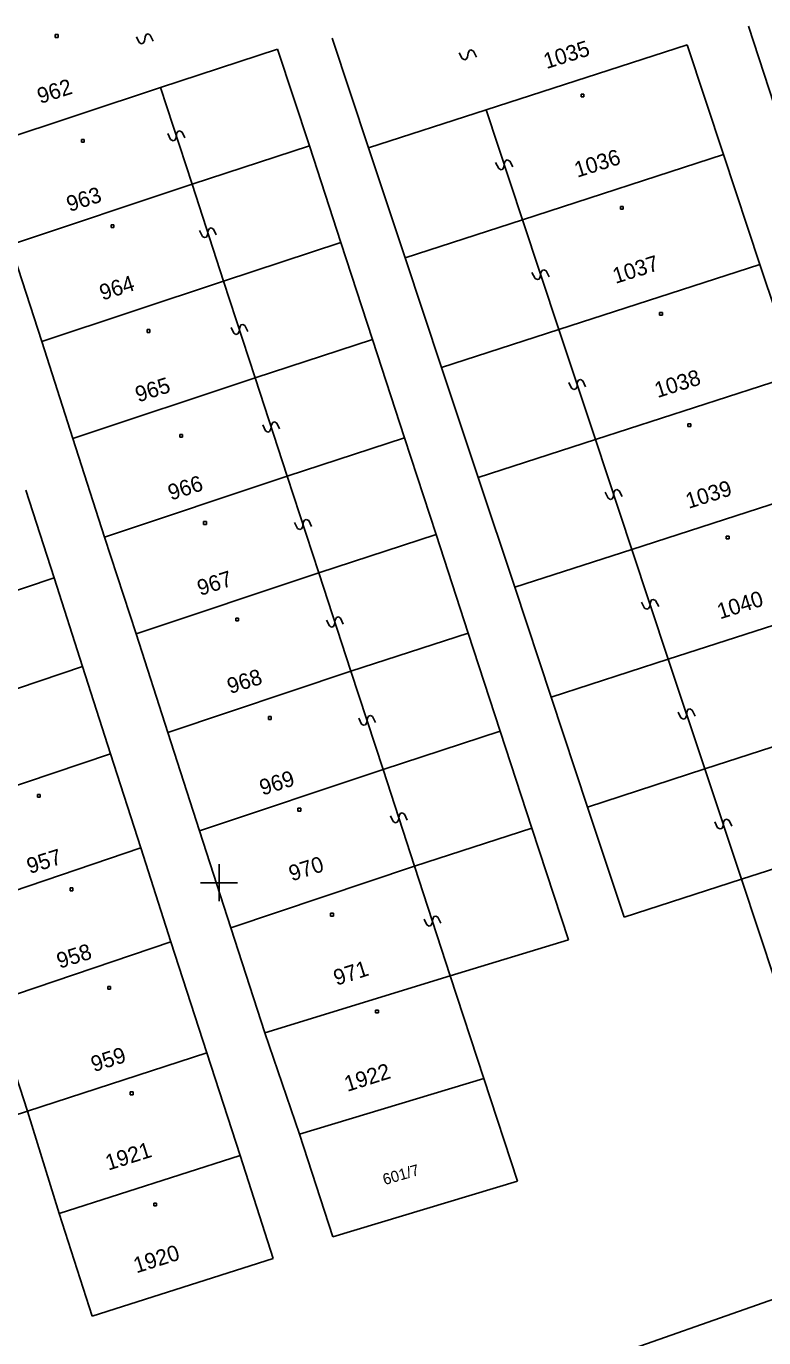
# Model space of a CAD drawing. Extents: x -493352 to -492964, y -1127001 to -1126712.
# Drawn here: x -493236.25 to -493212.33, y -1126754.75 to -1126712.25 of the extents above; entities that cross this region are included whole.
import ezdxf

# ---------------------------------------------------------------- set-up
doc = ezdxf.new("R2010")
doc.units = 0
doc.layers.add('katastrální mapa', color=7, linetype='Continuous')
doc.layers.add('síť', color=7, linetype='Continuous')

msp = doc.modelspace()

# ---------------------------------------------------------------- linework, layer by layer
at = {"layer": 'katastrální mapa'}
for p, q in [((-493212.83, -1126712.25), (-493211.66, -1126715.82)), ((-493235.31, -1126712.52), (-493235.22, -1126712.52)), ((-493235.31, -1126712.61), (-493235.31, -1126712.52)), ((-493235.22, -1126712.61), (-493235.31, -1126712.61)), ((-493235.22, -1126712.52), (-493235.22, -1126712.61)), ((-493232.59, -1126712.78), (-493232.68, -1126712.59)), ((-493232.52, -1126712.82), (-493232.59, -1126712.78)), ((-493232.46, -1126712.8), (-493232.52, -1126712.82)), ((-493232.42, -1126712.73), (-493232.46, -1126712.8)), ((-493232.4, -1126712.59), (-493232.42, -1126712.73)), ((-493232.36, -1126712.52), (-493232.4, -1126712.59)), ((-493232.3, -1126712.5), (-493232.36, -1126712.52)), ((-493232.23, -1126712.54), (-493232.3, -1126712.5)), ((-493232.14, -1126712.73), (-493232.23, -1126712.54)), ((-493226.33, -1126712.64), (-493225.15, -1126716.19)), ((-493221.34, -1126714.96), (-493214.82, -1126712.85)), ((-493214.82, -1126712.85), (-493213.64, -1126716.41)), ((-493231.9, -1126714.23), (-493228.1, -1126712.99)), ((-493228.1, -1126712.99), (-493227.07, -1126716.13)), ((-493222.11, -1126713.3), (-493222.21, -1126713.11)), ((-493221.94, -1126713.25), (-493221.98, -1126713.32)), ((-493221.92, -1126713.11), (-493221.94, -1126713.25)), ((-493221.88, -1126713.04), (-493221.92, -1126713.11)), ((-493221.83, -1126713.02), (-493221.88, -1126713.04)), ((-493221.75, -1126713.06), (-493221.83, -1126713.02)), ((-493221.65, -1126713.25), (-493221.75, -1126713.06)), ((-493222.03, -1126713.34), (-493222.11, -1126713.3)), ((-493221.98, -1126713.32), (-493222.03, -1126713.34)), ((-493237.78, -1126716.19), (-493231.9, -1126714.23)), ((-493231.9, -1126714.23), (-493230.87, -1126717.37)), ((-493218.26, -1126714.45), (-493218.17, -1126714.45)), ((-493218.26, -1126714.54), (-493218.26, -1126714.45)), ((-493218.17, -1126714.54), (-493218.26, -1126714.54)), ((-493218.17, -1126714.45), (-493218.17, -1126714.54)), ((-493225.15, -1126716.19), (-493221.34, -1126714.96)), ((-493221.34, -1126714.96), (-493220.16, -1126718.52)), ((-493231.57, -1126715.92), (-493231.66, -1126715.73)), ((-493231.38, -1126715.73), (-493231.39, -1126715.87)), ((-493231.34, -1126715.66), (-493231.38, -1126715.73)), ((-493231.28, -1126715.64), (-493231.34, -1126715.66)), ((-493231.2, -1126715.68), (-493231.28, -1126715.64)), ((-493231.11, -1126715.87), (-493231.2, -1126715.68)), ((-493234.46, -1126715.92), (-493234.37, -1126715.92)), ((-493234.46, -1126716.01), (-493234.46, -1126715.92)), ((-493234.37, -1126716.01), (-493234.46, -1126716.01)), ((-493234.37, -1126715.92), (-493234.37, -1126716.01)), ((-493231.49, -1126715.96), (-493231.57, -1126715.92)), ((-493231.43, -1126715.94), (-493231.49, -1126715.96)), ((-493231.39, -1126715.87), (-493231.43, -1126715.94)), ((-493230.87, -1126717.37), (-493227.07, -1126716.13)), ((-493227.07, -1126716.13), (-493226.05, -1126719.26)), ((-493225.15, -1126716.19), (-493223.96, -1126719.75)), ((-493220.93, -1126716.86), (-493221.03, -1126716.67)), ((-493220.74, -1126716.67), (-493220.76, -1126716.81)), ((-493220.7, -1126716.6), (-493220.74, -1126716.67)), ((-493220.65, -1126716.58), (-493220.7, -1126716.6)), ((-493220.57, -1126716.62), (-493220.65, -1126716.58)), ((-493220.47, -1126716.81), (-493220.57, -1126716.62)), ((-493220.16, -1126718.52), (-493213.64, -1126716.41)), ((-493213.64, -1126716.41), (-493212.46, -1126719.97)), ((-493220.85, -1126716.9), (-493220.93, -1126716.86)), ((-493220.8, -1126716.88), (-493220.85, -1126716.9)), ((-493220.76, -1126716.81), (-493220.8, -1126716.88)), ((-493236.76, -1126719.33), (-493230.87, -1126717.37)), ((-493230.87, -1126717.37), (-493229.85, -1126720.51)), ((-493216.98, -1126718.09), (-493216.89, -1126718.09)), ((-493216.98, -1126718.18), (-493216.98, -1126718.09)), ((-493216.89, -1126718.18), (-493216.98, -1126718.18)), ((-493216.89, -1126718.09), (-493216.89, -1126718.18)), ((-493233.5, -1126718.68), (-493233.41, -1126718.68)), ((-493233.5, -1126718.77), (-493233.5, -1126718.68)), ((-493233.41, -1126718.77), (-493233.5, -1126718.77)), ((-493233.41, -1126718.68), (-493233.41, -1126718.77)), ((-493230.31, -1126718.8), (-493230.35, -1126718.87)), ((-493230.25, -1126718.78), (-493230.31, -1126718.8)), ((-493230.18, -1126718.82), (-493230.25, -1126718.78)), ((-493223.96, -1126719.75), (-493220.16, -1126718.52)), ((-493220.16, -1126718.52), (-493218.98, -1126722.08)), ((-493230.54, -1126719.06), (-493230.63, -1126718.87)), ((-493230.47, -1126719.1), (-493230.54, -1126719.06)), ((-493230.41, -1126719.08), (-493230.47, -1126719.1)), ((-493230.37, -1126719.01), (-493230.41, -1126719.08)), ((-493230.35, -1126718.87), (-493230.37, -1126719.01)), ((-493230.09, -1126719.01), (-493230.18, -1126718.82)), ((-493236.76, -1126719.33), (-493235.75, -1126722.47)), ((-493229.85, -1126720.51), (-493226.05, -1126719.26)), ((-493226.05, -1126719.26), (-493225.02, -1126722.4)), ((-493223.96, -1126719.75), (-493222.78, -1126723.31)), ((-493218.98, -1126722.08), (-493212.46, -1126719.97)), ((-493212.46, -1126719.97), (-493211.27, -1126723.53)), ((-493219.75, -1126720.42), (-493219.85, -1126720.23)), ((-493219.67, -1126720.46), (-493219.75, -1126720.42)), ((-493219.62, -1126720.44), (-493219.67, -1126720.46)), ((-493219.58, -1126720.37), (-493219.62, -1126720.44)), ((-493219.56, -1126720.23), (-493219.58, -1126720.37)), ((-493219.52, -1126720.16), (-493219.56, -1126720.23)), ((-493219.47, -1126720.14), (-493219.52, -1126720.16)), ((-493219.39, -1126720.18), (-493219.47, -1126720.14)), ((-493219.29, -1126720.37), (-493219.39, -1126720.18)), ((-493235.75, -1126722.47), (-493229.85, -1126720.51)), ((-493229.85, -1126720.51), (-493228.83, -1126723.64)), ((-493215.71, -1126721.52), (-493215.62, -1126721.52)), ((-493215.71, -1126721.61), (-493215.71, -1126721.52)), ((-493215.62, -1126721.61), (-493215.71, -1126721.61)), ((-493215.62, -1126721.52), (-493215.62, -1126721.61)), ((-493232.33, -1126722.08), (-493232.24, -1126722.08)), ((-493232.33, -1126722.17), (-493232.33, -1126722.08)), ((-493232.24, -1126722.17), (-493232.33, -1126722.17)), ((-493232.24, -1126722.08), (-493232.24, -1126722.17)), ((-493229.52, -1126722.2), (-493229.61, -1126722.01)), ((-493229.45, -1126722.24), (-493229.52, -1126722.2)), ((-493229.35, -1126722.14), (-493229.39, -1126722.22)), ((-493229.33, -1126722.01), (-493229.35, -1126722.14)), ((-493229.29, -1126721.93), (-493229.33, -1126722.01)), ((-493229.23, -1126721.91), (-493229.29, -1126721.93)), ((-493229.16, -1126721.95), (-493229.23, -1126721.91)), ((-493229.07, -1126722.14), (-493229.16, -1126721.95)), ((-493222.78, -1126723.31), (-493218.98, -1126722.08)), ((-493218.98, -1126722.08), (-493217.79, -1126725.64)), ((-493235.75, -1126722.47), (-493234.74, -1126725.61)), ((-493229.39, -1126722.22), (-493229.45, -1126722.24)), ((-493228.83, -1126723.64), (-493225.02, -1126722.4)), ((-493225.02, -1126722.4), (-493223.98, -1126725.59)), ((-493222.78, -1126723.31), (-493221.6, -1126726.87)), ((-493234.74, -1126725.61), (-493228.83, -1126723.64)), ((-493228.83, -1126723.64), (-493227.79, -1126726.83)), ((-493218.57, -1126723.98), (-493218.66, -1126723.79)), ((-493218.38, -1126723.79), (-493218.39, -1126723.93)), ((-493218.34, -1126723.72), (-493218.38, -1126723.79)), ((-493218.28, -1126723.7), (-493218.34, -1126723.72)), ((-493218.2, -1126723.74), (-493218.28, -1126723.7)), ((-493218.11, -1126723.93), (-493218.2, -1126723.74)), ((-493217.79, -1126725.64), (-493211.27, -1126723.53)), ((-493218.49, -1126724.02), (-493218.57, -1126723.98)), ((-493218.43, -1126724), (-493218.49, -1126724.02)), ((-493218.39, -1126723.93), (-493218.43, -1126724)), ((-493228.49, -1126725.36), (-493228.58, -1126725.17)), ((-493228.3, -1126725.17), (-493228.32, -1126725.3)), ((-493228.26, -1126725.09), (-493228.3, -1126725.17)), ((-493228.2, -1126725.07), (-493228.26, -1126725.09)), ((-493228.13, -1126725.11), (-493228.2, -1126725.07)), ((-493228.04, -1126725.3), (-493228.13, -1126725.11)), ((-493214.79, -1126725.13), (-493214.7, -1126725.13)), ((-493214.79, -1126725.22), (-493214.79, -1126725.13)), ((-493214.7, -1126725.13), (-493214.7, -1126725.22)), ((-493231.27, -1126725.48), (-493231.18, -1126725.48)), ((-493231.27, -1126725.57), (-493231.27, -1126725.48)), ((-493231.18, -1126725.57), (-493231.27, -1126725.57)), ((-493231.18, -1126725.48), (-493231.18, -1126725.57)), ((-493228.42, -1126725.4), (-493228.49, -1126725.36)), ((-493228.36, -1126725.38), (-493228.42, -1126725.4)), ((-493228.32, -1126725.3), (-493228.36, -1126725.38)), ((-493227.79, -1126726.83), (-493223.98, -1126725.59)), ((-493223.98, -1126725.59), (-493222.96, -1126728.72)), ((-493214.7, -1126725.22), (-493214.79, -1126725.22)), ((-493234.74, -1126725.61), (-493233.71, -1126728.8)), ((-493221.6, -1126726.87), (-493217.79, -1126725.64)), ((-493217.79, -1126725.64), (-493216.61, -1126729.2)), ((-493233.71, -1126728.8), (-493227.79, -1126726.83)), ((-493227.79, -1126726.83), (-493226.76, -1126729.96)), ((-493221.6, -1126726.87), (-493220.41, -1126730.43)), ((-493236.27, -1126727.28), (-493235.35, -1126730.12)), ((-493217.15, -1126727.28), (-493217.19, -1126727.35)), ((-493217.1, -1126727.26), (-493217.15, -1126727.28)), ((-493217.02, -1126727.3), (-493217.1, -1126727.26)), ((-493216.92, -1126727.49), (-493217.02, -1126727.3)), ((-493216.61, -1126729.2), (-493210.09, -1126727.09)), ((-493217.38, -1126727.54), (-493217.48, -1126727.35)), ((-493217.3, -1126727.58), (-493217.38, -1126727.54)), ((-493217.25, -1126727.56), (-493217.3, -1126727.58)), ((-493217.21, -1126727.49), (-493217.25, -1126727.56)), ((-493217.19, -1126727.35), (-493217.21, -1126727.49)), ((-493230.5, -1126728.3), (-493230.41, -1126728.3)), ((-493230.5, -1126728.39), (-493230.5, -1126728.3)), ((-493230.41, -1126728.39), (-493230.5, -1126728.39)), ((-493230.41, -1126728.3), (-493230.41, -1126728.39)), ((-493227.46, -1126728.52), (-493227.55, -1126728.33)), ((-493227.38, -1126728.56), (-493227.46, -1126728.52)), ((-493227.32, -1126728.54), (-493227.38, -1126728.56)), ((-493227.28, -1126728.46), (-493227.32, -1126728.54)), ((-493227.27, -1126728.33), (-493227.28, -1126728.46)), ((-493227.23, -1126728.25), (-493227.27, -1126728.33)), ((-493227.17, -1126728.23), (-493227.23, -1126728.25)), ((-493227.09, -1126728.27), (-493227.17, -1126728.23)), ((-493227, -1126728.46), (-493227.09, -1126728.27)), ((-493233.71, -1126728.8), (-493232.69, -1126731.94)), ((-493226.76, -1126729.96), (-493222.96, -1126728.72)), ((-493222.96, -1126728.72), (-493221.92, -1126731.91)), ((-493213.55, -1126728.77), (-493213.46, -1126728.77)), ((-493213.55, -1126728.86), (-493213.55, -1126728.77)), ((-493213.46, -1126728.86), (-493213.55, -1126728.86)), ((-493213.46, -1126728.77), (-493213.46, -1126728.86)), ((-493220.41, -1126730.43), (-493216.61, -1126729.2)), ((-493216.61, -1126729.2), (-493215.43, -1126732.76)), ((-493241.19, -1126732.1), (-493235.35, -1126730.12)), ((-493235.35, -1126730.12), (-493234.43, -1126732.99)), ((-493232.69, -1126731.94), (-493226.76, -1126729.96)), ((-493226.76, -1126729.96), (-493225.72, -1126733.15)), ((-493220.41, -1126730.43), (-493219.23, -1126733.99)), ((-493215.43, -1126732.76), (-493208.91, -1126730.65)), ((-493216.2, -1126731.1), (-493216.3, -1126730.91)), ((-493216.12, -1126731.14), (-493216.2, -1126731.1)), ((-493216.07, -1126731.12), (-493216.12, -1126731.14)), ((-493216.03, -1126731.05), (-493216.07, -1126731.12)), ((-493216.01, -1126730.91), (-493216.03, -1126731.05)), ((-493215.97, -1126730.84), (-493216.01, -1126730.91)), ((-493215.92, -1126730.82), (-493215.97, -1126730.84)), ((-493215.84, -1126730.86), (-493215.92, -1126730.82)), ((-493215.74, -1126731.05), (-493215.84, -1126730.86)), ((-493229.46, -1126731.43), (-493229.37, -1126731.43)), ((-493229.46, -1126731.52), (-493229.46, -1126731.43)), ((-493229.37, -1126731.52), (-493229.46, -1126731.52)), ((-493229.37, -1126731.43), (-493229.37, -1126731.52)), ((-493226.42, -1126731.68), (-493226.51, -1126731.49)), ((-493226.23, -1126731.49), (-493226.25, -1126731.62)), ((-493226.19, -1126731.41), (-493226.23, -1126731.49)), ((-493226.13, -1126731.39), (-493226.19, -1126731.41)), ((-493226.06, -1126731.43), (-493226.13, -1126731.39)), ((-493225.97, -1126731.62), (-493226.06, -1126731.43)), ((-493232.69, -1126731.94), (-493231.66, -1126735.13)), ((-493226.35, -1126731.72), (-493226.42, -1126731.68)), ((-493226.29, -1126731.7), (-493226.35, -1126731.72)), ((-493226.25, -1126731.62), (-493226.29, -1126731.7)), ((-493225.72, -1126733.15), (-493221.92, -1126731.91)), ((-493221.92, -1126731.91), (-493220.88, -1126735.09)), ((-493219.23, -1126733.99), (-493215.43, -1126732.76)), ((-493215.43, -1126732.76), (-493214.24, -1126736.31)), ((-493240.26, -1126734.96), (-493234.43, -1126732.99)), ((-493234.43, -1126732.99), (-493233.52, -1126735.82)), ((-493231.66, -1126735.13), (-493225.72, -1126733.15)), ((-493225.72, -1126733.15), (-493224.68, -1126736.33)), ((-493219.23, -1126733.99), (-493218.05, -1126737.55)), ((-493215.02, -1126734.66), (-493215.11, -1126734.47)), ((-493214.83, -1126734.47), (-493214.84, -1126734.6)), ((-493214.79, -1126734.39), (-493214.83, -1126734.47)), ((-493214.73, -1126734.37), (-493214.79, -1126734.39)), ((-493214.65, -1126734.41), (-493214.73, -1126734.37)), ((-493214.56, -1126734.6), (-493214.65, -1126734.41)), ((-493214.24, -1126736.31), (-493207.73, -1126734.2)), ((-493228.4, -1126734.62), (-493228.31, -1126734.62)), ((-493228.4, -1126734.71), (-493228.4, -1126734.62)), ((-493228.31, -1126734.71), (-493228.4, -1126734.71)), ((-493228.31, -1126734.62), (-493228.31, -1126734.71)), ((-493225.38, -1126734.86), (-493225.47, -1126734.67)), ((-493225.31, -1126734.9), (-493225.38, -1126734.86)), ((-493225.25, -1126734.88), (-493225.31, -1126734.9)), ((-493225.21, -1126734.81), (-493225.25, -1126734.88)), ((-493225.19, -1126734.67), (-493225.21, -1126734.81)), ((-493225.15, -1126734.6), (-493225.19, -1126734.67)), ((-493225.09, -1126734.58), (-493225.15, -1126734.6)), ((-493225.02, -1126734.62), (-493225.09, -1126734.58)), ((-493224.93, -1126734.81), (-493225.02, -1126734.62)), ((-493214.94, -1126734.7), (-493215.02, -1126734.66)), ((-493214.88, -1126734.68), (-493214.94, -1126734.7)), ((-493214.84, -1126734.6), (-493214.88, -1126734.68)), ((-493231.66, -1126735.13), (-493230.63, -1126738.32)), ((-493224.68, -1126736.33), (-493220.88, -1126735.09)), ((-493220.88, -1126735.09), (-493219.86, -1126738.23)), ((-493239.34, -1126737.79), (-493233.52, -1126735.82)), ((-493233.52, -1126735.82), (-493232.54, -1126738.87)), ((-493230.63, -1126738.32), (-493224.68, -1126736.33)), ((-493224.68, -1126736.33), (-493223.66, -1126739.47)), ((-493218.05, -1126737.55), (-493214.24, -1126736.31)), ((-493214.24, -1126736.31), (-493213.05, -1126739.89)), ((-493235.89, -1126737.14), (-493235.8, -1126737.14)), ((-493235.89, -1126737.23), (-493235.89, -1126737.14)), ((-493235.8, -1126737.23), (-493235.89, -1126737.23)), ((-493235.8, -1126737.14), (-493235.8, -1126737.23)), ((-493227.44, -1126737.59), (-493227.35, -1126737.59)), ((-493227.44, -1126737.68), (-493227.44, -1126737.59)), ((-493227.35, -1126737.68), (-493227.44, -1126737.68)), ((-493227.35, -1126737.59), (-493227.35, -1126737.68)), ((-493224.35, -1126738.02), (-493224.44, -1126737.83)), ((-493224.16, -1126737.83), (-493224.18, -1126737.97)), ((-493224.12, -1126737.76), (-493224.16, -1126737.83)), ((-493224.06, -1126737.74), (-493224.12, -1126737.76)), ((-493223.99, -1126737.78), (-493224.06, -1126737.74)), ((-493223.9, -1126737.97), (-493223.99, -1126737.78)), ((-493218.05, -1126737.55), (-493216.86, -1126741.12)), ((-493213.05, -1126739.89), (-493206.54, -1126737.78)), ((-493230.63, -1126738.32), (-493229.62, -1126741.46)), ((-493224.28, -1126738.06), (-493224.35, -1126738.02)), ((-493224.22, -1126738.04), (-493224.28, -1126738.06)), ((-493224.18, -1126737.97), (-493224.22, -1126738.04)), ((-493223.66, -1126739.47), (-493219.86, -1126738.23)), ((-493219.86, -1126738.23), (-493218.67, -1126741.85)), ((-493213.83, -1126738.22), (-493213.92, -1126738.03)), ((-493213.75, -1126738.26), (-493213.83, -1126738.22)), ((-493213.69, -1126738.24), (-493213.75, -1126738.26)), ((-493213.65, -1126738.17), (-493213.69, -1126738.24)), ((-493213.64, -1126738.03), (-493213.65, -1126738.17)), ((-493213.6, -1126737.96), (-493213.64, -1126738.03)), ((-493213.54, -1126737.94), (-493213.6, -1126737.96)), ((-493213.46, -1126737.98), (-493213.54, -1126737.94)), ((-493213.37, -1126738.17), (-493213.46, -1126737.98)), ((-493238.35, -1126740.84), (-493232.54, -1126738.87)), ((-493232.54, -1126738.87), (-493231.56, -1126741.92)), ((-493229.62, -1126741.46), (-493223.66, -1126739.47)), ((-493223.66, -1126739.47), (-493222.5, -1126743.02)), ((-493216.86, -1126741.12), (-493213.05, -1126739.89)), ((-493213.05, -1126739.89), (-493211.95, -1126743.21)), ((-493234.83, -1126740.17), (-493234.74, -1126740.17)), ((-493234.83, -1126740.26), (-493234.83, -1126740.17)), ((-493234.74, -1126740.26), (-493234.83, -1126740.26)), ((-493234.74, -1126740.17), (-493234.74, -1126740.26)), ((-493226.38, -1126740.99), (-493226.29, -1126740.99)), ((-493226.38, -1126741.08), (-493226.38, -1126740.99)), ((-493226.29, -1126741.08), (-493226.38, -1126741.08)), ((-493226.29, -1126740.99), (-493226.29, -1126741.08)), ((-493223.26, -1126741.37), (-493223.35, -1126741.18)), ((-493223.09, -1126741.31), (-493223.13, -1126741.39)), ((-493223.07, -1126741.18), (-493223.09, -1126741.31)), ((-493223.03, -1126741.1), (-493223.07, -1126741.18)), ((-493222.97, -1126741.08), (-493223.03, -1126741.1)), ((-493222.9, -1126741.12), (-493222.97, -1126741.08)), ((-493222.81, -1126741.31), (-493222.9, -1126741.12)), ((-493229.62, -1126741.46), (-493228.52, -1126744.86)), ((-493223.19, -1126741.41), (-493223.26, -1126741.37)), ((-493223.13, -1126741.39), (-493223.19, -1126741.41)), ((-493237.36, -1126743.88), (-493231.56, -1126741.92)), ((-493231.56, -1126741.92), (-493230.4, -1126745.51)), ((-493222.5, -1126743.02), (-493218.67, -1126741.85)), ((-493228.52, -1126744.86), (-493222.5, -1126743.02)), ((-493222.5, -1126743.02), (-493221.41, -1126746.34)), ((-493233.61, -1126743.36), (-493233.52, -1126743.36)), ((-493233.61, -1126743.45), (-493233.61, -1126743.36)), ((-493233.52, -1126743.45), (-493233.61, -1126743.45)), ((-493233.52, -1126743.36), (-493233.52, -1126743.45)), ((-493237.36, -1126743.88), (-493236.21, -1126747.4)), ((-493224.92, -1126744.13), (-493224.83, -1126744.13)), ((-493224.92, -1126744.22), (-493224.92, -1126744.13)), ((-493224.83, -1126744.22), (-493224.92, -1126744.22)), ((-493224.83, -1126744.13), (-493224.83, -1126744.22)), ((-493228.52, -1126744.86), (-493227.39, -1126748.15)), ((-493236.21, -1126747.4), (-493230.4, -1126745.51)), ((-493230.4, -1126745.51), (-493229.32, -1126748.84)), ((-493227.39, -1126748.15), (-493221.41, -1126746.34)), ((-493221.41, -1126746.34), (-493220.32, -1126749.67)), ((-493232.88, -1126746.78), (-493232.79, -1126746.78)), ((-493232.88, -1126746.87), (-493232.88, -1126746.78)), ((-493232.79, -1126746.78), (-493232.79, -1126746.87)), ((-493232.79, -1126746.87), (-493232.88, -1126746.87)), ((-493240.01, -1126748.64), (-493236.21, -1126747.4)), ((-493236.21, -1126747.4), (-493235.19, -1126750.72)), ((-493228.16, -1126759.15), (-493196.45, -1126748.04)), ((-493227.39, -1126748.15), (-493226.31, -1126751.47)), ((-493235.19, -1126750.72), (-493229.32, -1126748.84)), ((-493229.32, -1126748.84), (-493228.24, -1126752.18)), ((-493226.31, -1126751.47), (-493220.32, -1126749.67)), ((-493232.12, -1126750.38), (-493232.03, -1126750.38)), ((-493232.12, -1126750.47), (-493232.12, -1126750.38)), ((-493232.03, -1126750.47), (-493232.12, -1126750.47)), ((-493232.03, -1126750.38), (-493232.03, -1126750.47)), ((-493235.19, -1126750.72), (-493234.11, -1126754.05)), ((-493234.11, -1126754.05), (-493228.24, -1126752.18))]:
    msp.add_line(p, q, dxfattribs=at)
at = {"layer": 'síť'}
for p, q in [((-493230, -1126739.4), (-493230, -1126740.6)), ((-493230.6, -1126740), (-493229.4, -1126740))]:
    msp.add_line(p, q, dxfattribs=at)

# ---------------------------------------------------------------- texts
at = {"layer": 'katastrální mapa'}
for s, height, rotation, p in [('1035', 0.51, 17.532, (-493219.38, -1126713.64)), ('962', 0.51, 17.766, (-493235.8, -1126714.77)), ('1036', 0.51, 17.532, (-493218.38, -1126717.16)), ('963', 0.51, 17.766, (-493234.85, -1126718.27)), ('1037', 0.51, 17.532, (-493217.14, -1126720.6)), ('964', 0.51, 17.766, (-493233.78, -1126721.14)), ('1038', 0.51, 17.532, (-493215.78, -1126724.3)), ('965', 0.51, 17.766, (-493232.62, -1126724.44)), ('966', 0.51, 17.766, (-493231.56, -1126727.62)), ('1039', 0.51, 17.532, (-493214.77, -1126727.89)), ('967', 0.51, 17.766, (-493230.61, -1126730.71)), ('1040', 0.51, 17.532, (-493213.75, -1126731.47)), ('968', 0.51, 17.766, (-493229.64, -1126733.89)), ('969', 0.51, 17.766, (-493228.59, -1126737.18)), ('957', 0.51, 17.586, (-493236.14, -1126739.72)), ('970', 0.51, 17.766, (-493227.64, -1126739.96)), ('958', 0.51, 17.586, (-493235.17, -1126742.79)), ('971', 0.51, 17.766, (-493226.19, -1126743.34)), ('959', 0.51, 17.586, (-493234.06, -1126746.14)), ('1922', 0.51, 17.532, (-493225.84, -1126746.78)), ('1921', 0.51, 17.532, (-493233.59, -1126749.33)), ('601/7', 0.36, 16.218, (-493224.63, -1126749.8)), ('1920', 0.51, 17.532, (-493232.68, -1126752.66))]:
    msp.add_text(s, height=height, rotation=rotation, dxfattribs=at).set_placement(p)

doc.saveas('drawing.dxf')
